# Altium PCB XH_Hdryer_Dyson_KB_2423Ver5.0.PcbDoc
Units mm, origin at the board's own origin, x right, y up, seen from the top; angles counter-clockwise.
Board outline 13.45 x 9.9 mm, 2 copper layers (Top, Bottom), stack 0.323 mm thick; 3 components, 2 nets, 6 pads, 14 vias.
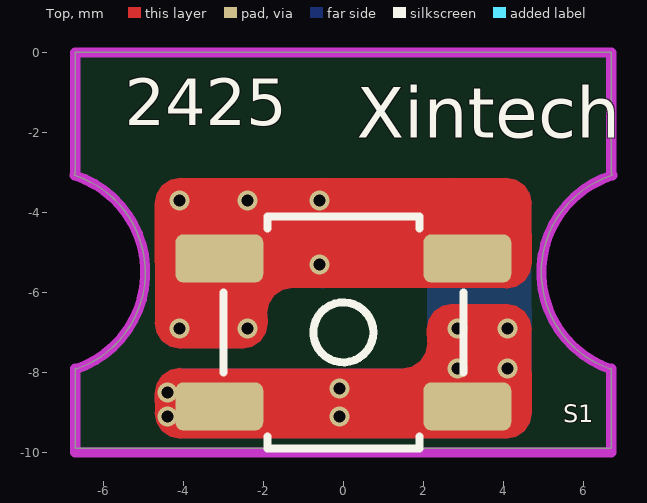
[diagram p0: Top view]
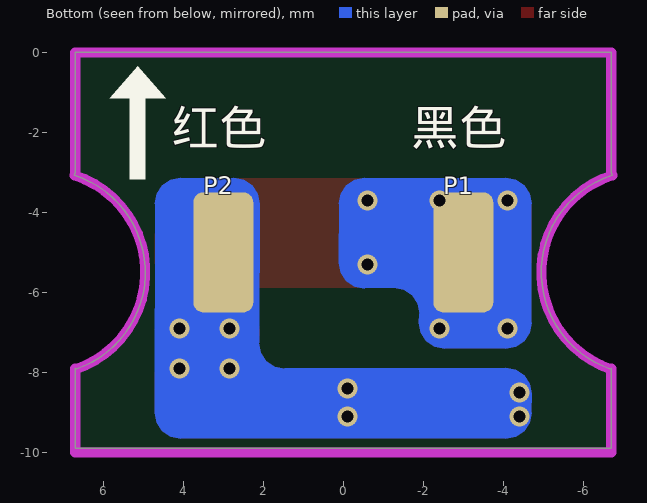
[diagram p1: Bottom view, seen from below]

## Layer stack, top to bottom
Solder Mask Top: solder mask 0.0102, Solder Resist, Dk 3.5
Top: signal copper 0.0343
Dielectric 1: dielectric 0.254, FR-4, Dk 4.3
Bottom: signal copper 0.0343
Solder Mask Bottom: solder mask 0.0102, Solder Resist, Dk 3.5

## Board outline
-6.7,-9.9 -6.7,-7.9 -6.694,-7.919 ccw(c-7.5,-5.5) -6.723,-3.072 -6.7,-3 -6.7,0 6.7,0 6.7,-3 6.723,-3.072 ccw(c7.5,-5.5) 6.693,-7.919 6.7,-7.9 6.7,-9.9

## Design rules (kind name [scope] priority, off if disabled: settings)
Clearance "Clearance - Default - DEFAULT- SMD" [IsVia vs IsSMTPin] p1: gap=0.152 ignorepadtopadclearanceinfootprint=FALSE
Clearance "Clearance - Default - DEFAULT - Via" [IsVia vs IsVia] p2: gap=0.152 ignorepadtopadclearanceinfootprint=FALSE
Clearance "Clearance - Default - DEFAULT - Net" [All] p3: gap=0.152 ignorepadtopadclearanceinfootprint=FALSE except(0: Arc-Hole Track-Hole SMDPad-Hole THPad-Hole Via-Hole Fill-Hole Poly-Hole Region-Hole Text-Hole; 0.254: Text-Text)
ComponentClearance "ComponentClearance - Default - DEFAULT" [All] p1: gap=0.152 collisioncheckmode=3 verticalgap=0.254 showdistances=FALSE
HoleToHoleClearance "HoleToHoleClearance - Default - DEFAULT" [All] p1: gap=0.152 allowstackedmicrovias=TRUE
Length "Default Length" [All] p1: maxlimit=1270 minlimit=0
MaxMinImpedance "Default Impedance" [All] p1: minimum=50.00 maximum=150.0
ParallelSegment "Default Parallel Segment Same Layer" [All] p1: limit=25.4 gap=5.08
ParallelSegment "Default Parallel Segment Adjasent" [All] p2: limit=25.4 gap=5.08
PlaneConnect "Default PlaneConnect" [All] p1: planeconnectstyle=Relief reliefexpansion=0.508 reliefentries=4 reliefconductorwidth=0.381 reliefairgap=0.254
PolygonConnect "PolygonConnect - Default SMT" [IsSMTPin] p1: connectstyle=Relief reliefconductorwidth=0.254 reliefentries=4 polygonreliefangle="45 Angle" airgapwidth=0.254
PolygonConnect "PolygonConnect - Default Pad" [All] p2: connectstyle=Relief reliefconductorwidth=0.381 reliefentries=4 polygonreliefangle="45 Angle" airgapwidth=0.254
RoutingLayers "RoutingLayers - Default - DEFAULT" [All] p1: top layer_v5=TRUE bottom layer_v5=TRUE
RoutingPriority "RoutingPriority - Default - DEFAULT" [All] p1: routingpriority=3
RoutingTopology "Default Routing Topology" [All] p1: topology=Shortest
RoutingVias "RoutingVias - Default - DEFAULT" [All] p1: holewidth=0.94 width=1.397 viastyle="Through Hole" minholewidth=0.94 minwidth=1.397 maxholewidth=0.94 maxwidth=1.397
SMDToCorner "SMDToCorner - Default - DEFAULT" [All] p1: distance=60000
SolderMaskExpansion "SolderMaskExpansion from CAM settings" [All] p1: expansion=0.127 istentingtop=FALSE
Width "Default Width" [All] p1: maxlimit=2 minlimit=0.3 preferedwidth=1
24 further rules are at their usual default settings.

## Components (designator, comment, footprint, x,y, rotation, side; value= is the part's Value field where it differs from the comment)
P1 "CON_FPAD_2" CON_FPAD_2 -3,-5 r180 bottom
P2 "CON_FPAD_2" CON_FPAD_2 3,-5 r180 bottom
S1 "SW_SMD_5.2X5.2" SW_SMD_5.2X5.2 0,-7 r0 top

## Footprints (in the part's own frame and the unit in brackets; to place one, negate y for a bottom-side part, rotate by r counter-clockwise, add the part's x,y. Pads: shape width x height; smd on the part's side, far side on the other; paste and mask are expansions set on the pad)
CON_FPAD_2 [mm]
  rrect33% 1.5x3 smd: 1(0,0)
SW_SMD_5.2X5.2 [mm]
  rrect33% 2.2x1.2 smd mask+0.05: 1(-3.1,-1.85) 2(3.1,-1.85) 3(3.1,1.85) 4(-3.1,1.85)
  silkscreen extent -3,-2.9 3,2.9

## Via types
v1: diameter 0.5, hole 0.3, Top to Bottom, tented both sides, 14 vias

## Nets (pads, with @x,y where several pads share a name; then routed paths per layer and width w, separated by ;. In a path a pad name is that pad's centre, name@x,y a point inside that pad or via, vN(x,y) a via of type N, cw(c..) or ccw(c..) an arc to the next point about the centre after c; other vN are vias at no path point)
$$$1: P2.1 S1.1 S1.2 | length 10.4
  Top w1: S1.1 S1.2 2.85,-8.85 v1(2.85,-6.9)
  Bottom w1: v1(2.85,-6.9) 2.85,-5 P2.1
  other v1: -4.4,-9.1 -0.1,-9.1 -4.4,-8.5 -0.1,-8.4 2.85,-7.9 4.1,-7.9 4.1,-6.9
$$$2: P1.1 S1.3 S1.4 | length 6.3
  Top w1: S1.4@-3.1,-5.2 S1.4 S1.3
  other v1: -4.1,-6.9 -2.4,-6.9 -0.6,-5.3 -4.1,-3.7 -2.4,-3.7 -0.6,-3.7

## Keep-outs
Keep-Out Layer:
  lines w0.254: -6.723,-3.072 cw(c-7.5,-5.5) -6.694,-7.919 ; -6.7,-7.9 -6.7,-10 0,-10 6.7,-10 6.7,-7.9 ; -6.7,-3 -6.7,0 0,0 6.7,0 6.7,-3 ; 6.693,-7.919 cw(c7.5,-5.5) 6.723,-3.072

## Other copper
Top:
  region net $$$1: -4.065,-9.662 -4.313,-9.613 -4.523,-9.473 -4.663,-9.263 -4.712,-9.015 -4.7,-9.015 -4.712,-8.535 -4.663,-8.287 -4.523,-8.077 -4.313,-7.937 -4.065,-7.888 -4.065,-7.9 1.465,-7.912 1.713,-7.863 1.923,-7.723 2.063,-7.513 2.112,-7.265 2.1,-7.265 2.088,-6.935 2.137,-6.687 2.277,-6.477 2.487,-6.337 2.735,-6.288 2.735,-6.3 4.065,-6.288 4.313,-6.337 4.523,-6.477 4.663,-6.687 4.712,-6.935 4.7,-6.935 4.712,-9.015 4.663,-9.263 4.523,-9.473 4.313,-9.613 4.065,-9.662 4.065,-9.65 -4.065,-9.65
  region net $$$2: -4.065,-7.412 -4.313,-7.363 -4.523,-7.223 -4.663,-7.013 -4.712,-6.765 -4.7,-6.765 -4.712,-3.785 -4.663,-3.537 -4.523,-3.327 -4.313,-3.187 -4.065,-3.138 -4.065,-3.15 4.065,-3.138 4.313,-3.187 4.523,-3.327 4.663,-3.537 4.712,-3.785 4.7,-3.785 4.712,-5.265 4.663,-5.513 4.523,-5.723 4.313,-5.863 4.065,-5.912 4.065,-5.9 -1.265,-5.888 -1.513,-5.937 -1.723,-6.077 -1.863,-6.287 -1.912,-6.535 -1.9,-6.535 -1.888,-6.765 -1.937,-7.013 -2.077,-7.223 -2.287,-7.363 -2.535,-7.412 -2.535,-7.4 -4.065,-7.4
Bottom:
  region net $$$1: 1.465,-7.912 1.713,-7.863 1.923,-7.723 2.063,-7.513 2.112,-7.265 2.1,-7.265 2.088,-3.785 2.137,-3.537 2.277,-3.327 2.487,-3.187 2.735,-3.138 2.735,-3.15 4.065,-3.138 4.313,-3.187 4.523,-3.327 4.663,-3.537 4.712,-3.785 4.7,-3.785 4.712,-9.015 4.663,-9.263 4.523,-9.473 4.313,-9.613 4.065,-9.662 4.065,-9.65 -4.065,-9.662 -4.313,-9.613 -4.523,-9.473 -4.663,-9.263 -4.712,-9.015 -4.7,-9.015 -4.712,-8.535 -4.663,-8.287 -4.523,-8.077 -4.313,-7.937 -4.065,-7.888 -4.065,-7.9 1.465,-7.9
  region net $$$2: -4.712,-3.785 -4.663,-3.537 -4.523,-3.327 -4.313,-3.187 -4.065,-3.138 -4.065,-3.15 -0.535,-3.138 -0.287,-3.187 -0.077,-3.327 0.063,-3.537 0.112,-3.785 0.1,-3.785 0.112,-5.265 0.063,-5.513 -0.077,-5.723 -0.287,-5.863 -0.535,-5.912 -0.535,-5.9 -1.265,-5.888 -1.513,-5.937 -1.723,-6.077 -1.863,-6.287 -1.912,-6.535 -1.9,-6.535 -1.888,-6.765 -1.937,-7.013 -2.077,-7.223 -2.287,-7.363 -2.535,-7.412 -2.535,-7.4 -4.065,-7.412 -4.313,-7.363 -4.523,-7.223 -4.663,-7.013 -4.712,-6.765 -4.7,-6.765 -4.7,-3.785

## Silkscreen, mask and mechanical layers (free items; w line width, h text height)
Silkscreen Top:
  text "Xintech" at 0.33,-2.13 h1.27
  text "2425" at -5.461,-2.206 h2
Silkscreen Bottom:
  region: 4.953,-3.175 4.953,-1.143 5.334,-1.143 5.334,-3.175
  region: 4.445,-1.143 5.139,-0.344 5.842,-1.143
  text "黑色" at -1.7,-2.6 h1.5
  text "红色" at 4.3,-2.6 h1.5
Drill Drawing:
  lines w0.025: -7,0 -6.999,0 ; 7,0 7.001,0 ; 7,0 7.001,0 ; 7,-10 7.001,-10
